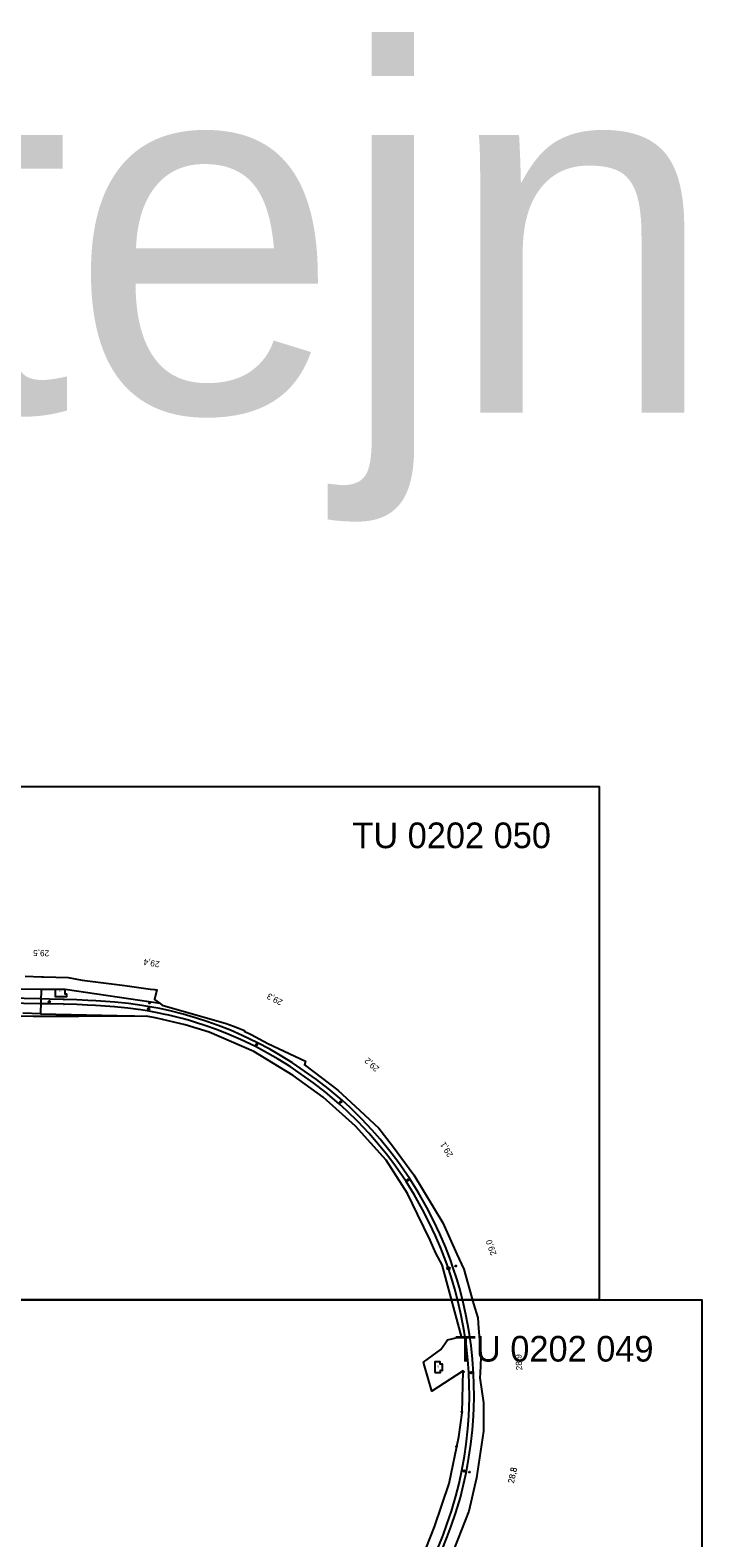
# Model space of a CAD drawing. Extents: x -768800 to -748700, y -1061452 to -1051366.
# Drawn here: x -762454 to -761800, y -1058232 to -1056763 of the extents above; entities that cross this region are included whole.
import ezdxf

# ---------------------------------------------------------------- set-up
doc = ezdxf.new("R2010")
doc.units = 0
for name, color, linetype in [('Vrstva 1', 7, 'Continuous'), ('Vrstva 2', 7, 'Continuous'), ('Vrstva 49', 7, 'Continuous'), ('Vrstva 53', 7, 'Continuous'), ('Vrstva 55', 7, 'Continuous'), ('Vrstva 57', 7, 'Continuous'), ('Vrstva 7', 7, 'Continuous')]:
    doc.layers.add(name, color=color, linetype=linetype)

msp = doc.modelspace()

# ---------------------------------------------------------------- linework, layer by layer
at = {"layer": 'Vrstva 1'}
for points in [[(-762600, -1058000), (-762600, -1057500), (-761900, -1057500), (-761900, -1058000), (-762600, -1058000)], [(-762443.5, -1057711.6), (-762444.6, -1057711.6), (-762476.3, -1057711)], [(-762443.5, -1057706.8), (-762444.6, -1057706.8), (-762475.1, -1057706.2)], [(-762052.7, -1058242.9), (-762047.8, -1058230.7), (-762043.9, -1058220.3), (-762039.4, -1058206.9), (-762035.1, -1058192.3), (-762032, -1058179.8), (-762029.2, -1058167), (-762026.7, -1058153.1), (-762024.8, -1058140.5), (-762023.3, -1058126.6), (-762022.3, -1058113.1), (-762021.9, -1058105), (-762021.7, -1058094.6), (-762021.9, -1058081.8), (-762022.3, -1058071.9), (-762023.3, -1058057.7), (-762024.7, -1058044.4), (-762026.8, -1058029.4), (-762029.6, -1058014.3), (-762032.6, -1058001), (-762036, -1057988.2), (-762038.3, -1057980.4), (-762042.4, -1057967.9), (-762044.8, -1057960.8), (-762049.7, -1057948.2), (-762055, -1057935.7), (-762061.1, -1057922.7), (-762067.6, -1057909.9), (-762076, -1057895.1), (-762084.3, -1057882), (-762090, -1057873.6), (-762096, -1057865.1), (-762103.6, -1057855.2), (-762113.3, -1057843.4), (-762120.9, -1057834.7), (-762131.3, -1057823.6), (-762142.5, -1057812.6), (-762150.3, -1057805.5), (-762163.7, -1057794), (-762175, -1057785.2), (-762198.5, -1057769), (-762210.1, -1057761.8), (-762220.7, -1057755.8), (-762232.7, -1057749.5), (-762247.4, -1057742.4), (-762259, -1057737.4), (-762270.9, -1057732.7), (-762281.8, -1057728.8), (-762291.8, -1057725.6), (-762298.3, -1057723.6), (-762305, -1057721.7), (-762317.6, -1057718.5), (-762327.6, -1057716.3), (-762337.5, -1057714.4), (-762345.3, -1057713.2), (-762358.2, -1057711.4), (-762371.6, -1057710), (-762385, -1057709), (-762390, -1057708.7), (-762397.9, -1057708.2), (-762408.4, -1057707.7), (-762420.8, -1057707.3), (-762435.2, -1057707), (-762443.5, -1057706.8)], [(-762056.8, -1058241.2), (-762051.9, -1058229), (-762048.1, -1058218.7), (-762043.7, -1058205.6), (-762039.5, -1058191.1), (-762036.3, -1058178.6), (-762033.6, -1058166), (-762031.1, -1058152.2), (-762029.3, -1058140.3), (-762027.7, -1058125.6), (-762026.8, -1058112.8), (-762026.5, -1058104.7), (-762026.3, -1058094.8), (-762026.4, -1058081.8), (-762026.8, -1058071.8), (-762026.9, -1058070.8), (-762027.8, -1058058.2), (-762029.2, -1058045.2), (-762031.3, -1058030.3), (-762034.2, -1058015.2), (-762037.1, -1058002.2), (-762040.4, -1057989.4), (-762042.7, -1057981.7), (-762046.7, -1057969.2), (-762049.2, -1057962.3), (-762054, -1057949.7), (-762059.2, -1057937.6), (-762065.1, -1057925.1), (-762071.8, -1057912), (-762080.1, -1057897.3), (-762088, -1057884.7), (-762093.7, -1057876.2), (-762099.9, -1057867.5), (-762107.1, -1057858), (-762116.8, -1057846.2), (-762124.2, -1057837.7), (-762134.6, -1057826.6), (-762145.7, -1057815.8), (-762153.2, -1057808.9), (-762166.5, -1057797.6), (-762177.8, -1057788.7), (-762200.7, -1057772.7), (-762212.4, -1057765.5), (-762222.7, -1057759.6), (-762234.5, -1057753.3), (-762249.2, -1057746.3), (-762260.6, -1057741.3), (-762272.5, -1057736.7), (-762283.8, -1057732.6), (-762292.9, -1057729.7), (-762299.9, -1057727.6), (-762306, -1057725.9), (-762318.8, -1057722.7), (-762324.2, -1057721.5), (-762328.4, -1057720.6), (-762338.1, -1057718.8), (-762346.1, -1057717.5), (-762358.8, -1057715.8), (-762371.8, -1057714.5), (-762385.5, -1057713.5), (-762390.4, -1057713.2), (-762398.2, -1057712.8), (-762408.3, -1057712.4), (-762421.1, -1057712), (-762435.2, -1057711.7), (-762443.5, -1057711.6)], [(-762500, -1058500), (-762500, -1058000), (-761800, -1058000), (-761800, -1058500), (-762500, -1058500)]]:
    msp.add_lwpolyline(points, dxfattribs=at)
at = {"layer": 'Vrstva 53'}
for p, q in [((-762014.4, -1058055.1), (-762014.3, -1058055.1)), ((-762032.2, -1058070.1), (-762032.1, -1058070.1)), ((-762033.8, -1058109), (-762033.7, -1058109)), ((-762038.9, -1058142.8), (-762038.8, -1058142.8))]:
    msp.add_line(p, q, dxfattribs=at)
for points in [[(-762458.7, -1057684.5), (-762442.8, -1057685.3), (-762441.9, -1057685.4), (-762440.9, -1057685.4), (-762416.9, -1057686), (-762403.2, -1057688.5), (-762361.6, -1057693.9), (-762336.6, -1057697.2), (-762332.5, -1057697.7), (-762331.5, -1057697.8), (-762330.7, -1057697.9), (-762332.9, -1057707.3), (-762327.4, -1057711.3), (-762325.3, -1057712.9), (-762265.3, -1057730.1), (-762263, -1057730.8), (-762256, -1057733.2), (-762250.2, -1057735.6), (-762245.3, -1057737.7), (-762245.6, -1057738.3), (-762238.6, -1057741.6), (-762222.4, -1057750.1), (-762185.7, -1057767.5), (-762186.8, -1057771), (-762154.4, -1057795.6), (-762133, -1057815.5), (-762114.5, -1057832.8), (-762101.2, -1057849.9), (-762080.5, -1057878.1), (-762052.2, -1057925), (-762038.4, -1057955.4), (-762031.8, -1057970), (-762022.2, -1058003.8), (-762018.2, -1058017.5), (-762017.4, -1058027.6), (-762016.4, -1058038.9), (-762016.2, -1058041.6), (-762016, -1058043.6), (-762015, -1058056.1), (-762015.8, -1058071.3), (-762016, -1058075.8), (-762012.5, -1058100.2), (-762012.6, -1058127.7), (-762019.3, -1058173.1), (-762026.9, -1058205.6), (-762048.4, -1058260.1)], [(-762068.7, -1058242.3), (-762060.2, -1058221), (-762046, -1058178.9), (-762036.5, -1058133.3), (-762033.2, -1058109.9), (-762032.3, -1058069), (-762038.9, -1058073.2), (-762062.7, -1058088.7), (-762070, -1058064), (-762071.1, -1058060.6), (-762054, -1058048.2), (-762049.6, -1058041.6), (-762047.5, -1058038.8), (-762038, -1058036.6), (-762034, -1058035.6), (-762052.8, -1057965.8), (-762059, -1057954.4), (-762064.6, -1057941.7), (-762076.8, -1057916.3), (-762086.7, -1057896.2), (-762107.4, -1057863.7), (-762137.1, -1057830.6), (-762168.6, -1057802.6), (-762197.8, -1057781.4), (-762236.1, -1057758), (-762279.6, -1057739.1), (-762303, -1057731.9), (-762330.7, -1057725.7), (-762340.7, -1057723.5), (-762406.4, -1057723.9), (-762451.1, -1057723.8), (-762475.8, -1057723.3)]]:
    msp.add_lwpolyline(points, dxfattribs=at)
for centre in [(-762014.4, -1058055.1), (-762032.1, -1058070.1), (-762033.7, -1058109), (-762038.9, -1058142.8)]:
    msp.add_circle(centre, 0.499, dxfattribs=at)
at = {"layer": 'Vrstva 55'}
msp.add_line((-762443.7, -1057721.3), (-762460.9, -1057720.6), dxfattribs=at)
for points in [[(-762443.2, -1057697.5), (-762517.2, -1057697.1), (-762548.2, -1057696.2), (-762563.8, -1057696.3), (-762568.2, -1057694.4)], [(-762429.7, -1057697.5), (-762443.2, -1057697.5), (-762443.7, -1057721.3)], [(-762327.4, -1057711.3), (-762419.8, -1057697.7), (-762429.7, -1057697.5)], [(-762429.7, -1057697.5), (-762429.6, -1057704.3), (-762418.1, -1057704.3), (-762418.1, -1057702.1), (-762419.8, -1057702.1), (-762419.8, -1057697.7)], [(-762443.7, -1057721.3), (-762354.3, -1057723.2), (-762352.2, -1057723.3), (-762340.7, -1057723.5)], [(-762060, -1058070.5), (-762054.5, -1058070.5), (-762054.5, -1058068.5), (-762052.6, -1058068.6), (-762052.5, -1058062.6), (-762054.7, -1058062.6), (-762054.7, -1058060.4), (-762060, -1058060.4), (-762060, -1058070.5)]]:
    msp.add_lwpolyline(points, dxfattribs=at)
at = {"layer": 'Vrstva 7'}
for p, q in [((-762435.2, -1057709.4), (-762435.3, -1057709.4)), ((-762337.6, -1057710.9), (-762337.7, -1057710.9)), ((-762233.5, -1057751.4), (-762233.6, -1057751.4)), ((-762151.6, -1057807.2), (-762151.7, -1057807.2)), ((-762086, -1057883.2), (-762086.1, -1057883.2)), ((-762039.6, -1057966.9), (-762039.6, -1057966.8)), ((-762024.7, -1058070.8), (-762024.7, -1058070.7)), ((-762026.1, -1058167.7), (-762026.1, -1058167.6))]:
    msp.add_line(p, q, dxfattribs=at)
for centre, radius in [((-762435.2, -1057709.4), 0.75), ((-762435.2, -1057709.4), 0.5), ((-762337.7, -1057710.9), 0.5), ((-762338.6, -1057716.5), 0.75), ((-762233.5, -1057751.4), 0.75), ((-762233.5, -1057751.4), 0.5), ((-762151.7, -1057807.2), 0.75), ((-762151.7, -1057807.2), 0.5), ((-762086.1, -1057883.2), 0.75), ((-762086.1, -1057883.2), 0.5), ((-762046.7, -1057969.2), 1.25), ((-762046.7, -1057969.2), 0.752), ((-762039.6, -1057966.9), 0.5), ((-762024.7, -1058070.8), 0.75), ((-762024.7, -1058070.8), 0.5), ((-762031.4, -1058166.5), 0.75), ((-762026.1, -1058167.6), 0.5)]:
    msp.add_circle(centre, radius, dxfattribs=at)

# ---------------------------------------------------------------- texts
at = {"layer": 'Vrstva 1'}
for s, rotation, p in [('2', 178.1595, (-762420.3, -1057706.2)), ('1', 178.3081, (-762420.2, -1057710.9))]:
    msp.add_text(s, height=2.5, rotation=rotation, dxfattribs=at).set_placement(p)
at = {"layer": 'Vrstva 2'}
for s, p in [('TU 0202 050', (-762140.2, -1057560)), ('TU 0202 049', (-762040.3, -1058060))]:
    msp.add_text(s, height=25, dxfattribs=at).set_placement(p)
at = {"layer": 'Vrstva 49'}
msp.add_text('Karlštejn', height=352, dxfattribs=at).set_placement((-763617.9, -1057135.8))
at = {"layer": 'Vrstva 57'}
for s, rotation, p in [('144', 180, (-762422.6, -1057698.3)), ('143', 93.6498, (-762056.1, -1058067.1))]:
    msp.add_text(s, height=1.5, rotation=rotation, dxfattribs=at).set_placement(p)
at = {"layer": 'Vrstva 7'}
for s, rotation, p in [('29,5', 178.8102, (-762435.3, -1057659.4)), ('29,4', 170.619, (-762327.5, -1057670.3)), ('29,3', 152.2068, (-762207.5, -1057708.2)), ('29,2', 137.4736, (-762113.5, -1057774)), ('29,1', 122.1181, (-762041.9, -1057858.6)), ('29,0', 109.468, (-761999.7, -1057955.3)), ('28,9', 93.1591, (-761974.8, -1058068.3)), ('28,8', 79.2238, (-761983, -1058179)), ('28,8', 77.7485, (-761983, -1058179))]:
    msp.add_text(s, height=6, rotation=rotation, dxfattribs=at).set_placement(p)

doc.saveas('drawing.dxf')
